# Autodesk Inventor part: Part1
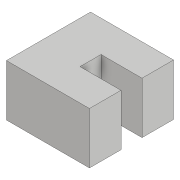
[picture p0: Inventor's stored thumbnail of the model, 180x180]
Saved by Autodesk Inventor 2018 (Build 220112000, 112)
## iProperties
Created: 2015-07
Part Number: Part1
Material: Generic
Document SubType Name: Modeling
Designer: Sandeep
Density: 1 g/cm^3
Appearance: Default
Author: Sandeep
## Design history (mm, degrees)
sketch "Sketch1"
  geometry: L1 (0, 0)-(-30, 0); L2 (-30, 0)-(-30, 40); L3 (-30, 40)-(0, 40); L4 (0, 40)-(0, 0)
  constraints: 8 end point, 2 parallel, 1 horizontal, 1 perpendicular
  dimensions: "d0" = 30 distance between parallel lines of L4 L2; "d1" = 40 distance of L1.end L2.end
extrude "Extrusion1" new body sketch "Sketch1" distance "d2" = 15; taper "d3" = 0 deg
sketch "Sketch2"
  geometry: L1 (0, 40)-(0, 0) reference; L2 (-15, 0)-(-15, 40) reference; L3 (0, 0)-(-15, 0) reference; L4 (-15, 15)-(0, 15); L5 (0, 15)-(0, 25); L6 (0, 25)-(-15, 25); L7 (-15, 25)-(-15, 15)
  constraints: 8 end point, 2 parallel, 2 point on line, 1 horizontal, 1 perpendicular
  dimensions: "d4" = 10 distance between parallel lines of L6 L4; "d5" = 15 distance between parallel lines of L3 L4
extrude "Extrusion2" cut sketch "Sketch2" distance "d6" = 10; taper "d7" = 0 deg
node "Direct Edit2"
body "Solid1"
feature "Size2" dims "d9" = 9.5
